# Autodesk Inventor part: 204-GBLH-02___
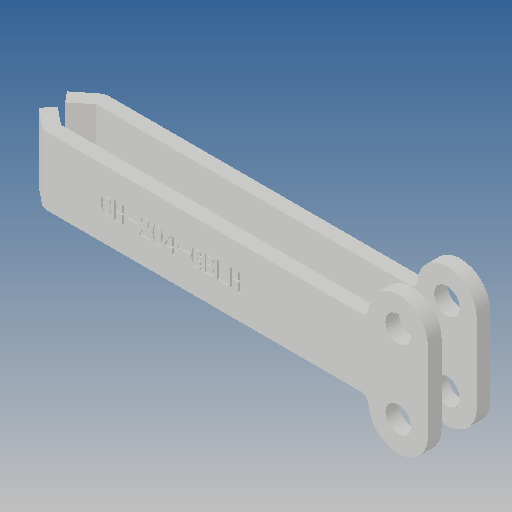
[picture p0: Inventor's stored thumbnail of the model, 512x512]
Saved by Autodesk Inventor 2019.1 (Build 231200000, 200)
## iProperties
Created: 2012-09
Part Number: 204-GBLH-02___
Material: Ogólny
Document SubType Name: Modeling
Designer: CADENGINEERING4
Density: 1 g/cm^3
Appearance: Domyślna
Author: CADENGINEERING4
Revision Number: ÈÎºÎ
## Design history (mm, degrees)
feature "NONE" [ÊäÈë]
feature "ÊäÈë2"
node "Bryła1"
node "Bryła2"
